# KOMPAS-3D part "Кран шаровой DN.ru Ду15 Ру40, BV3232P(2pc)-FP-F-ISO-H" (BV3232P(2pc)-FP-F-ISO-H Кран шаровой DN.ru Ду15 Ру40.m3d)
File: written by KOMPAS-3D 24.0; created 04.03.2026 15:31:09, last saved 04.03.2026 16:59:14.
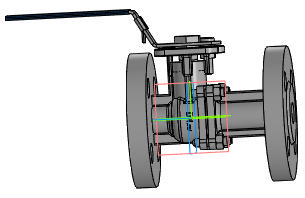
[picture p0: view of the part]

Document properties: Автор: R2D2; Полное имя файла: BV3232P(2pc)-FP-F-ISO-H Кран шаровой DN.ru Ду15 Ру40.cdw

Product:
- Part/product: Кран шаровой DN.ru Ду15 Ру40  | designation BV3232P(2pc)-FP-F-ISO-H
    Масса: 2.16
    Раздел спецификации: Прочие изделия
    Форматы листов документа: A3
    Примечание: D160-22129

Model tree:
1. Операция без истории:2

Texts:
  BV3232P(2pc)-FP-F-ISO-H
